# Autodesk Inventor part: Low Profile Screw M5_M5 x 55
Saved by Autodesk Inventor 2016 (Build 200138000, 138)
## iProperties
Created: 2016-03
Part Number: Low Profile Screw M5_M5 x 55
Material: Generic
Document SubType Name: Modeling
Designer: bongo_000
Density: 1 g/cm^3
Appearance: Default
Author: bongo_000
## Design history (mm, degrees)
feature "CUT-EXTRUDE2"
body "Solid1"
